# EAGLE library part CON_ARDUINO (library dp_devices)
Arduino board connector layout
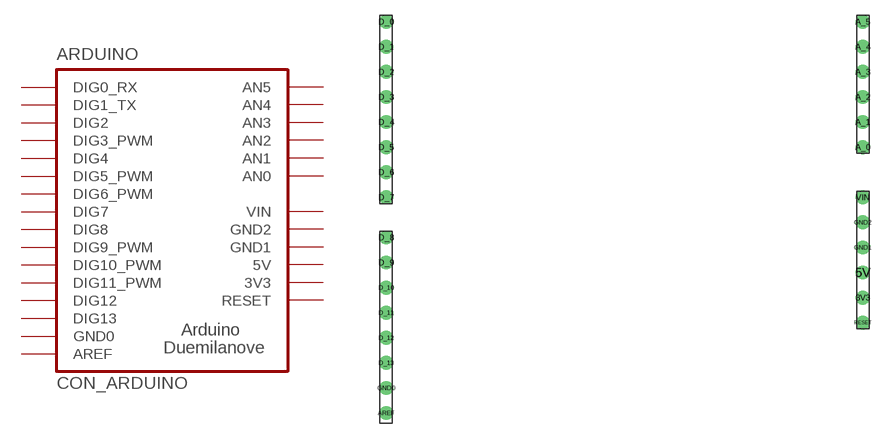
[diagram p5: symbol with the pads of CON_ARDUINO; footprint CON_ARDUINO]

Designator prefix ARDUINO

## CON_ARDUINO  [CON_ARDUINO]
3V3  3V3
5V  5V
A_0  AN0  in
A_1  AN1  in
A_2  AN2  in
A_3  AN3  in
A_4  AN4  in
A_5  AN5  in
AREF  AREF
D_0  DIG0_RX
D_1  DIG1_TX
D_2  DIG2
D_3  DIG3_PWM
D_4  DIG4
D_5  DIG5_PWM
D_6  DIG6_PWM
D_7  DIG7
D_8  DIG8
D_9  DIG9_PWM
D_10  DIG10_PWM
D_11  DIG11_PWM
D_12  DIG12
D_13  DIG13
GND0  GND0  sup
GND1  GND1  sup
GND2  GND2  sup
RESET  RESET  in
VIN  VIN  pwr

## Footprint CON_ARDUINO (pad centres in mm)
drill 0.8 pad 1.4 round: 3V3 25.4,-12.7; 5V 25.4,-10.16; A_0 25.4,2.54; A_1 25.4,5.08; A_2 25.4,7.62; A_3 25.4,10.16; A_4 25.4,12.7; A_5 25.4,15.24; AREF -22.86,-24.384; D_0 -22.86,15.24; D_1 -22.86,12.7; D_2 -22.86,10.16; D_3 -22.86,7.62; D_4 -22.86,5.08; D_5 -22.86,2.54; D_6 -22.86,0; D_7 -22.86,-2.54; D_8 -22.86,-6.604; D_9 -22.86,-9.144; D_10 -22.86,-11.684; D_11 -22.86,-14.224; D_12 -22.86,-16.764; D_13 -22.86,-19.304; GND0 -22.86,-21.844; GND1 25.4,-7.62; GND2 25.4,-5.08; RESET 25.4,-15.24; VIN 25.4,-2.54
